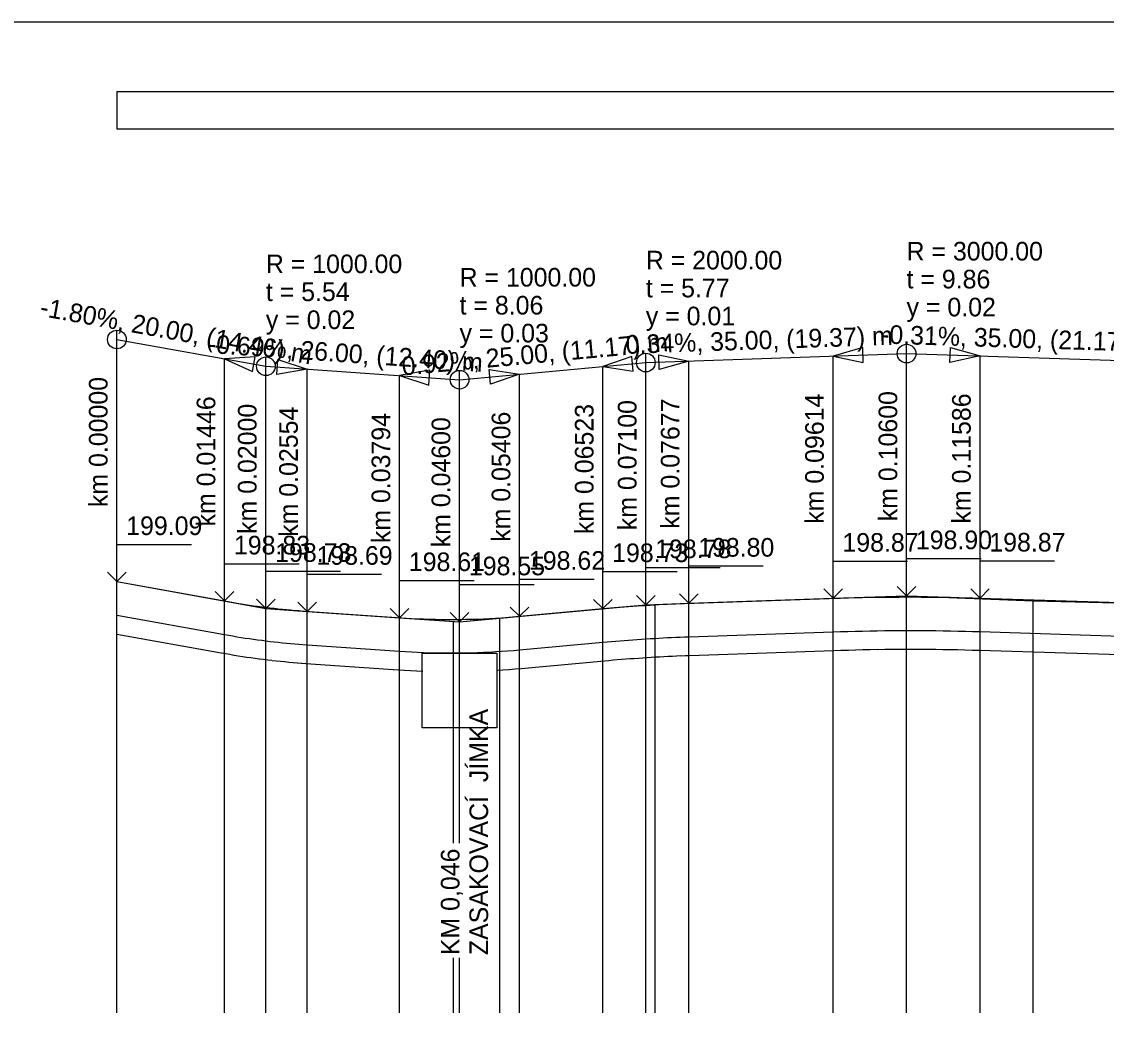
# Model space of a CAD drawing. Extents: x -51 to 53, y -74 to 15.
# Drawn here: x -39.72 to -25.16, y 1.63 to 15.15 of the extents above; entities that cross this region are included whole.
import ezdxf

# ---------------------------------------------------------------- set-up
doc = ezdxf.new("R2010")
doc.units = 0
for name, color, linetype in [('Implicitní', 7, 'Continuous'), ('KONSTRUKCE_L', 7, 'Continuous'), ('KOTY_L', 7, 'Continuous'), ('Nová vrstva (0)', 7, 'Continuous'), ('SKLON_POMERY', 7, 'Continuous'), ('TABULKY_L', 7, 'Continuous'), ('TEREN_L', 7, 'Continuous'), ('V_POLYGON', 7, 'Continuous'), ('V_POLYGON_ZO', 7, 'Continuous')]:
    doc.layers.add(name, color=color, linetype=linetype)

msp = doc.modelspace()

# ---------------------------------------------------------------- linework, layer by layer
at = {"layer": 'Implicitní'}
msp.add_lwpolyline([(-51.392, 15.154), (53.079, 15.154), (53.079, -14.546), (-51.392, -14.546)], close=True, dxfattribs=at)
at = {"layer": 'KONSTRUKCE_L'}
for p, q in [((-38.44, 7.189), (-36.994, 6.929)), ((-36.994, 6.929), (-36.938, 6.919)), ((-36.938, 6.919), (-36.883, 6.909)), ((-36.883, 6.909), (-36.828, 6.9)), ((-36.828, 6.9), (-36.772, 6.891)), ((-36.772, 6.891), (-36.717, 6.882)), ((-36.717, 6.882), (-36.662, 6.874)), ((-36.662, 6.874), (-36.606, 6.866)), ((-36.606, 6.866), (-36.551, 6.859)), ((-36.551, 6.859), (-36.495, 6.851)), ((-36.495, 6.851), (-36.44, 6.844)), ((-36.44, 6.844), (-36.385, 6.837)), ((-31.744, 6.841), (-31.686, 6.846)), ((-31.686, 6.846), (-31.629, 6.85)), ((-31.629, 6.85), (-31.571, 6.855)), ((-31.571, 6.855), (-31.513, 6.859)), ((-31.513, 6.859), (-31.455, 6.863)), ((-31.455, 6.863), (-31.398, 6.867)), ((-31.398, 6.867), (-31.34, 6.87)), ((-31.34, 6.87), (-31.282, 6.874)), ((-31.282, 6.874), (-31.225, 6.877)), ((-31.225, 6.877), (-31.167, 6.881)), ((-31.167, 6.881), (-31.109, 6.884)), ((-31.109, 6.884), (-31.051, 6.887)), ((-31.051, 6.887), (-30.994, 6.889)), ((-30.994, 6.889), (-30.936, 6.892)), ((-30.936, 6.892), (-30.878, 6.894)), ((-30.878, 6.894), (-30.821, 6.897)), ((-30.821, 6.897), (-30.763, 6.899)), ((-30.763, 6.899), (-28.826, 6.965)), ((-28.826, 6.965), (-28.727, 6.968)), ((-28.727, 6.968), (-28.629, 6.971)), ((-28.629, 6.971), (-28.53, 6.974)), ((-28.53, 6.974), (-28.431, 6.976)), ((-28.431, 6.976), (-28.333, 6.978)), ((-28.333, 6.978), (-28.234, 6.979)), ((-28.234, 6.979), (-28.136, 6.981)), ((-28.136, 6.981), (-28.037, 6.982)), ((-28.037, 6.982), (-27.939, 6.982)), ((-27.939, 6.982), (-27.84, 6.983)), ((-27.84, 6.983), (-27.741, 6.983)), ((-27.741, 6.983), (-27.643, 6.982)), ((-27.643, 6.982), (-27.544, 6.982)), ((-27.544, 6.982), (-27.446, 6.981)), ((-27.446, 6.981), (-27.347, 6.979)), ((-27.347, 6.979), (-27.249, 6.978)), ((-27.249, 6.978), (-27.15, 6.976)), ((-27.15, 6.976), (-27.051, 6.973)), ((-27.051, 6.973), (-26.953, 6.971)), ((-26.953, 6.971), (-26.854, 6.968)), ((-26.854, 6.968), (-24.738, 6.901)), ((-36.385, 6.837), (-36.329, 6.831)), ((-36.329, 6.831), (-36.274, 6.825)), ((-36.274, 6.825), (-36.218, 6.819)), ((-36.218, 6.819), (-36.163, 6.813)), ((-36.163, 6.813), (-36.108, 6.808)), ((-36.108, 6.808), (-36.052, 6.803)), ((-36.052, 6.803), (-35.997, 6.799)), ((-35.997, 6.799), (-35.942, 6.794)), ((-35.942, 6.794), (-35.886, 6.79)), ((-35.886, 6.79), (-34.646, 6.705)), ((-34.646, 6.705), (-34.566, 6.699)), ((-34.566, 6.699), (-34.485, 6.695)), ((-33.437, 6.694), (-33.356, 6.699)), ((-33.356, 6.699), (-33.276, 6.704)), ((-33.276, 6.704), (-33.195, 6.709)), ((-33.195, 6.709), (-33.114, 6.716)), ((-33.114, 6.716), (-33.034, 6.723)), ((-33.034, 6.723), (-31.917, 6.826)), ((-31.917, 6.826), (-31.859, 6.831)), ((-31.859, 6.831), (-31.802, 6.836)), ((-31.802, 6.836), (-31.744, 6.841)), ((-34.485, 6.695), (-34.404, 6.691)), ((-34.404, 6.691), (-34.324, 6.688)), ((-34.324, 6.688), (-34.243, 6.685)), ((-34.243, 6.685), (-34.162, 6.683)), ((-34.162, 6.683), (-34.082, 6.681)), ((-34.082, 6.681), (-34.001, 6.681)), ((-34.001, 6.681), (-33.921, 6.681)), ((-33.921, 6.681), (-33.84, 6.681)), ((-33.84, 6.681), (-33.759, 6.683)), ((-33.759, 6.683), (-33.679, 6.684)), ((-33.679, 6.684), (-33.598, 6.687)), ((-33.598, 6.687), (-33.518, 6.69)), ((-33.518, 6.69), (-33.437, 6.694))]:
    msp.add_line(p, q, dxfattribs=at)
at = {"layer": 'KOTY_L'}
for p, q in [((-38.44, 1.849), (-38.44, 7.639)), ((-27.84, 1.849), (-27.84, 7.449)), ((-27.84, 1.849), (-27.84, 7.449)), ((-36.994, 1.849), (-36.994, 7.379)), ((-36.994, 1.849), (-36.994, 7.379)), ((-31.34, 1.849), (-31.34, 7.329)), ((-31.213, 1.849), (-31.213, 7.333)), ((-30.763, 1.849), (-30.763, 7.349)), ((-30.763, 1.849), (-30.763, 7.349)), ((-28.826, 1.849), (-28.826, 7.415)), ((-26.854, 1.849), (-26.854, 7.408)), ((-26.14, 1.849), (-26.14, 7.379)), ((-36.44, 1.849), (-36.44, 7.279)), ((-35.886, 1.849), (-35.886, 7.24)), ((-34.646, 1.849), (-34.646, 7.155)), ((-33.3, 1.849), (-33.3, 7.148)), ((-33.034, 1.849), (-33.034, 7.173)), ((-31.917, 1.849), (-31.917, 7.276)), ((-33.921, 4.127), (-33.921, 7.104)), ((-33.84, 4.127), (-33.84, 7.099)), ((-33.921, 1.849), (-33.921, 2.59)), ((-33.84, 1.849), (-33.84, 2.59))]:
    msp.add_line(p, q, dxfattribs=at)
at = {"layer": 'Nová vrstva (0)'}
for p, q in [((-38.44, 6.935), (-37.038, 6.682)), ((-30.754, 6.649), (-28.817, 6.715)), ((-28.818, 6.715), (-28.719, 6.718)), ((-28.72, 6.718), (-28.621, 6.721)), ((-28.622, 6.721), (-28.523, 6.724)), ((-28.524, 6.724), (-28.426, 6.726)), ((-28.427, 6.726), (-28.328, 6.728)), ((-28.329, 6.728), (-28.23, 6.73)), ((-28.231, 6.729), (-28.132, 6.731)), ((-28.133, 6.731), (-28.035, 6.732)), ((-28.036, 6.732), (-27.937, 6.732)), ((-27.938, 6.732), (-27.839, 6.733)), ((-27.84, 6.733), (-27.741, 6.733)), ((-27.742, 6.733), (-27.644, 6.732)), ((-27.645, 6.732), (-27.546, 6.732)), ((-27.547, 6.732), (-27.448, 6.731)), ((-27.449, 6.731), (-27.35, 6.729)), ((-27.351, 6.729), (-27.253, 6.728)), ((-27.254, 6.728), (-27.155, 6.726)), ((-27.156, 6.726), (-27.057, 6.723)), ((-27.058, 6.723), (-26.959, 6.721)), ((-26.96, 6.721), (-26.862, 6.718)), ((-26.862, 6.718), (-24.816, 6.654)), ((-37.037, 6.682), (-36.982, 6.673)), ((-36.981, 6.672), (-36.925, 6.663)), ((-36.924, 6.663), (-36.869, 6.653)), ((-36.867, 6.653), (-36.812, 6.644)), ((-36.811, 6.644), (-36.755, 6.635)), ((-36.754, 6.635), (-36.699, 6.627)), ((-36.697, 6.627), (-36.642, 6.619)), ((-36.64, 6.619), (-36.585, 6.611)), ((-36.584, 6.611), (-36.528, 6.603)), ((-36.527, 6.603), (-36.472, 6.596)), ((-36.47, 6.596), (-36.415, 6.589)), ((-36.413, 6.589), (-36.358, 6.583)), ((-36.357, 6.582), (-36.301, 6.576)), ((-36.3, 6.576), (-36.245, 6.57)), ((-36.243, 6.57), (-36.188, 6.565)), ((-36.187, 6.565), (-36.131, 6.559)), ((-36.13, 6.559), (-36.074, 6.554)), ((-36.073, 6.554), (-36.018, 6.55)), ((-33.011, 6.474), (-31.894, 6.577)), ((-31.895, 6.577), (-31.837, 6.582)), ((-31.838, 6.582), (-31.78, 6.587)), ((-31.781, 6.587), (-31.723, 6.592)), ((-31.724, 6.592), (-31.666, 6.596)), ((-31.667, 6.596), (-31.609, 6.601)), ((-31.61, 6.601), (-31.552, 6.605)), ((-31.553, 6.605), (-31.495, 6.609)), ((-31.496, 6.609), (-31.438, 6.613)), ((-31.439, 6.613), (-31.381, 6.617)), ((-31.382, 6.617), (-31.324, 6.621)), ((-31.325, 6.621), (-31.267, 6.625)), ((-31.268, 6.624), (-31.21, 6.628)), ((-31.211, 6.628), (-31.153, 6.631)), ((-31.154, 6.631), (-31.096, 6.634)), ((-31.097, 6.634), (-31.039, 6.637)), ((-31.04, 6.637), (-30.982, 6.64)), ((-30.983, 6.64), (-30.925, 6.642)), ((-30.926, 6.642), (-30.868, 6.645)), ((-30.869, 6.644), (-30.811, 6.647)), ((-30.812, 6.647), (-30.754, 6.649)), ((-36.016, 6.55), (-35.961, 6.545)), ((-35.959, 6.545), (-35.904, 6.541)), ((-35.903, 6.541), (-34.663, 6.455)), ((-34.662, 6.455), (-34.582, 6.45)), ((-34.58, 6.45), (-34.499, 6.445)), ((-34.497, 6.445), (-34.417, 6.441)), ((-34.415, 6.441), (-34.334, 6.438)), ((-33.34, 6.449), (-33.26, 6.454)), ((-33.258, 6.454), (-33.177, 6.46)), ((-33.175, 6.46), (-33.095, 6.467)), ((-33.093, 6.467), (-33.012, 6.474))]:
    msp.add_line(p, q, dxfattribs=at)
msp.add_lwpolyline([(-34.34, 6.677), (-33.34, 6.677), (-33.34, 5.677), (-34.34, 5.677)], close=True, dxfattribs=at)
at = {"layer": 'SKLON_POMERY'}
for p, q in [((-38.44, 10.889), (-38.44, 11.014)), ((-38.44, 7.639), (-38.44, 10.889)), ((-38.44, 10.889), (-36.44, 10.529)), ((-27.84, 10.699), (-27.84, 10.824)), ((-36.994, 7.379), (-36.994, 10.629)), ((-36.44, 10.529), (-36.44, 10.654)), ((-31.34, 10.579), (-31.34, 10.704)), ((-31.34, 10.579), (-27.84, 10.699)), ((-28.826, 7.415), (-28.826, 10.665)), ((-27.84, 7.449), (-27.84, 10.699)), ((-27.84, 10.699), (-24.34, 10.589)), ((-26.854, 7.418), (-26.854, 10.668)), ((-36.44, 7.279), (-36.44, 10.529)), ((-36.44, 10.529), (-33.84, 10.349)), ((-35.886, 7.24), (-35.886, 10.49)), ((-33.84, 10.349), (-31.34, 10.579)), ((-31.917, 7.276), (-31.917, 10.526)), ((-31.34, 7.329), (-31.34, 10.579)), ((-30.763, 7.349), (-30.763, 10.599)), ((-34.646, 7.155), (-34.646, 10.405)), ((-33.84, 10.349), (-33.84, 10.474)), ((-33.84, 7.099), (-33.84, 10.349)), ((-33.034, 7.173), (-33.034, 10.423))]:
    msp.add_line(p, q, dxfattribs=at)
for points in [[(-28.826, 10.665), (-28.423, 10.579), (-28.429, 10.779), (-28.826, 10.665)], [(-26.854, 10.668), (-27.257, 10.58), (-27.251, 10.78), (-26.854, 10.668)], [(-36.994, 10.629), (-36.618, 10.459), (-36.582, 10.656), (-36.994, 10.629)], [(-31.917, 10.526), (-31.51, 10.463), (-31.528, 10.662), (-31.917, 10.526)], [(-30.763, 10.599), (-31.159, 10.485), (-31.166, 10.685), (-30.763, 10.599)], [(-35.886, 10.49), (-36.292, 10.418), (-36.278, 10.618), (-35.886, 10.49)], [(-33.034, 10.423), (-33.423, 10.287), (-33.441, 10.486), (-33.034, 10.423)], [(-34.646, 10.405), (-34.254, 10.277), (-34.24, 10.477), (-34.646, 10.405)]]:
    msp.add_lwpolyline(points, close=True, dxfattribs=at)
for points in [[(-38.565, 7.764), (-38.44, 7.639), (-38.315, 7.764), (-38.44, 7.639), (-38.44, 8.139), (-37.44, 8.139)], [(-37.119, 7.504), (-36.994, 7.379), (-36.869, 7.504), (-36.994, 7.379), (-36.994, 7.879), (-35.994, 7.879)], [(-28.951, 7.54), (-28.826, 7.415), (-28.701, 7.54), (-28.826, 7.415), (-28.826, 7.915), (-27.826, 7.915)], [(-27.965, 7.574), (-27.84, 7.449), (-27.715, 7.574), (-27.84, 7.449), (-27.84, 7.949), (-26.84, 7.949)], [(-26.979, 7.543), (-26.854, 7.418), (-26.729, 7.543), (-26.854, 7.418), (-26.854, 7.918), (-25.854, 7.918)], [(-36.565, 7.404), (-36.44, 7.279), (-36.315, 7.404), (-36.44, 7.279), (-36.44, 7.779), (-35.44, 7.779)], [(-36.011, 7.365), (-35.886, 7.24), (-35.761, 7.365), (-35.886, 7.24), (-35.886, 7.74), (-34.886, 7.74)], [(-32.042, 7.401), (-31.917, 7.276), (-31.792, 7.401), (-31.917, 7.276), (-31.917, 7.776), (-30.917, 7.776)], [(-31.465, 7.454), (-31.34, 7.329), (-31.215, 7.454), (-31.34, 7.329), (-31.34, 7.829), (-30.34, 7.829)], [(-30.888, 7.474), (-30.763, 7.349), (-30.638, 7.474), (-30.763, 7.349), (-30.763, 7.849), (-29.763, 7.849)], [(-34.771, 7.28), (-34.646, 7.155), (-34.521, 7.28), (-34.646, 7.155), (-34.646, 7.655), (-33.646, 7.655)], [(-33.965, 7.224), (-33.84, 7.099), (-33.715, 7.224), (-33.84, 7.099), (-33.84, 7.599), (-32.84, 7.599)], [(-33.159, 7.298), (-33.034, 7.173), (-32.909, 7.298), (-33.034, 7.173), (-33.034, 7.673), (-32.034, 7.673)]]:
    msp.add_lwpolyline(points, dxfattribs=at)
for centre in [(-38.44, 10.889), (-27.84, 10.699), (-36.44, 10.529), (-31.34, 10.579), (-33.84, 10.349)]:
    msp.add_circle(centre, 0.125, dxfattribs=at)
at = {"layer": 'TABULKY_L'}
for p, q in [((-38.44, 14.218), (-38.44, 13.718)), ((-38.44, 14.218), (50.86, 14.218)), ((-38.44, 13.718), (50.86, 13.718))]:
    msp.add_line(p, q, dxfattribs=at)
at = {"layer": 'TEREN_L'}
for p, q in [((-38.44, 7.639), (-36.44, 7.279)), ((-31.34, 7.329), (-27.84, 7.449)), ((-27.84, 7.449), (-26.14, 7.379)), ((-33.84, 7.099), (-31.34, 7.329)), ((-26.14, 7.379), (-24.34, 7.339)), ((-36.44, 7.279), (-33.84, 7.099))]:
    msp.add_line(p, q, dxfattribs=at)
at = {"layer": 'V_POLYGON'}
for p, q in [((-38.44, 7.639), (-36.994, 7.379)), ((-30.763, 7.349), (-28.826, 7.415)), ((-26.854, 7.418), (-24.738, 7.351)), ((-35.886, 7.24), (-34.646, 7.155)), ((-33.034, 7.173), (-31.917, 7.276))]:
    msp.add_line(p, q, dxfattribs=at)
for points in [[(-28.826, 7.415), (-28.727, 7.418), (-28.629, 7.421), (-28.53, 7.424), (-28.431, 7.426), (-28.333, 7.428), (-28.234, 7.429), (-28.136, 7.431), (-28.037, 7.432), (-27.939, 7.432), (-27.84, 7.433), (-27.741, 7.433), (-27.643, 7.432), (-27.544, 7.432), (-27.446, 7.431), (-27.347, 7.429), (-27.249, 7.428), (-27.15, 7.426), (-27.051, 7.423), (-26.953, 7.421), (-26.854, 7.418)], [(-36.994, 7.379), (-36.938, 7.369), (-36.883, 7.359), (-36.828, 7.35), (-36.772, 7.341), (-36.717, 7.332), (-36.662, 7.324), (-36.606, 7.316), (-36.551, 7.309), (-36.495, 7.301), (-36.44, 7.294), (-36.385, 7.287), (-36.329, 7.281), (-36.274, 7.275), (-36.218, 7.269), (-36.163, 7.263), (-36.108, 7.258), (-36.052, 7.253), (-35.997, 7.249), (-35.942, 7.244), (-35.886, 7.24)], [(-31.917, 7.276), (-31.859, 7.281), (-31.802, 7.286), (-31.744, 7.291), (-31.686, 7.296), (-31.629, 7.3), (-31.571, 7.305), (-31.513, 7.309), (-31.455, 7.313), (-31.398, 7.317), (-31.34, 7.32), (-31.282, 7.324), (-31.225, 7.327), (-31.167, 7.331), (-31.109, 7.334), (-31.051, 7.337), (-30.994, 7.339), (-30.936, 7.342), (-30.878, 7.344), (-30.821, 7.347), (-30.763, 7.349)], [(-34.646, 7.155), (-34.566, 7.149), (-34.485, 7.145), (-34.404, 7.141), (-34.324, 7.138), (-34.243, 7.135), (-34.162, 7.133), (-34.082, 7.131), (-34.001, 7.131), (-33.921, 7.131), (-33.84, 7.131), (-33.759, 7.133), (-33.679, 7.134), (-33.598, 7.137), (-33.518, 7.14), (-33.437, 7.144), (-33.356, 7.149), (-33.276, 7.154), (-33.195, 7.159), (-33.114, 7.166), (-33.034, 7.173)]]:
    msp.add_lwpolyline(points, dxfattribs=at)
at = {"layer": 'V_POLYGON_ZO'}
for p, q in [((-28.826, 7.415), (-27.84, 7.449)), ((-27.84, 7.449), (-26.854, 7.418)), ((-36.994, 7.379), (-36.44, 7.279)), ((-31.917, 7.276), (-31.34, 7.329)), ((-31.34, 7.329), (-30.763, 7.349)), ((-36.44, 7.279), (-35.886, 7.24)), ((-34.646, 7.155), (-33.84, 7.099)), ((-33.84, 7.099), (-33.034, 7.173))]:
    msp.add_line(p, q, dxfattribs=at)

# ---------------------------------------------------------------- texts
at = {"layer": 'Nová vrstva (0)'}
for s, p in [('ZASAKOVACÍ  JÍMKA', (-33.457, 2.625)), ('KM 0,046', (-33.841, 2.625))]:
    msp.add_text(s, height=0.25, rotation=90, dxfattribs=at).set_placement(p)
at = {"layer": 'SKLON_POMERY'}
for s, p in [('R = 3000.00', (-27.84, 11.949)), ('R = 1000.00', (-36.44, 11.779)), ('R = 2000.00', (-31.34, 11.829)), ('R = 1000.00', (-33.84, 11.599)), ('t = 9.86', (-27.84, 11.574)), ('t = 5.54', (-36.44, 11.404)), ('t = 5.77', (-31.34, 11.454)), ('t = 8.06', (-33.84, 11.224)), ('y = 0.02', (-27.84, 11.199)), ('y = 0.02', (-36.44, 11.029)), ('y = 0.01', (-31.34, 11.079)), ('y = 0.03', (-33.84, 10.849)), ('199.09', (-38.315, 8.264)), ('198.90', (-27.715, 8.074)), ('198.83', (-36.869, 8.004)), ('198.73', (-36.315, 7.904)), ('198.73', (-31.792, 7.901)), ('198.78', (-31.215, 7.954)), ('198.80', (-30.638, 7.974)), ('198.87', (-28.701, 8.04)), ('198.87', (-26.729, 8.043)), ('198.69', (-35.761, 7.865)), ('198.61', (-34.521, 7.78)), ('198.62', (-32.909, 7.798)), ('198.55', (-33.715, 7.724))]:
    msp.add_text(s, height=0.25, dxfattribs=at).set_placement(p)
for s, rotation, p in [('-1.80%, 20.00, (14.46) m', 349.796, (-39.485, 11.208)), ('0.34%, 35.00, (19.37) m', 1.9636, (-31.606, 10.695)), ('-0.31%, 35.00, (21.17) m', 358.1999, (-28.185, 10.835)), ('-0.69%, 26.00, (12.40) m', 356.0397, (-37.226, 10.709)), ('0.92%, 25.00, (11.17) m', 5.2564, (-34.605, 10.405)), ('km 0.00000', 90, (-38.565, 8.639)), ('km 0.01446', 90, (-37.119, 8.379)), ('km 0.07100', 90, (-31.465, 8.329)), ('km 0.07677', 90, (-30.888, 8.349)), ('km 0.09614', 90, (-28.951, 8.415)), ('km 0.10600', 90, (-27.965, 8.449)), ('km 0.11586', 90, (-26.979, 8.418)), ('km 0.02000', 90, (-36.565, 8.279)), ('km 0.02554', 90, (-36.011, 8.24)), ('km 0.05406', 90, (-33.159, 8.173)), ('km 0.06523', 90, (-32.042, 8.276)), ('km 0.03794', 90, (-34.771, 8.155)), ('km 0.04600', 90, (-33.965, 8.099))]:
    msp.add_text(s, height=0.25, rotation=rotation, dxfattribs=at).set_placement(p)

doc.saveas('drawing.dxf')
